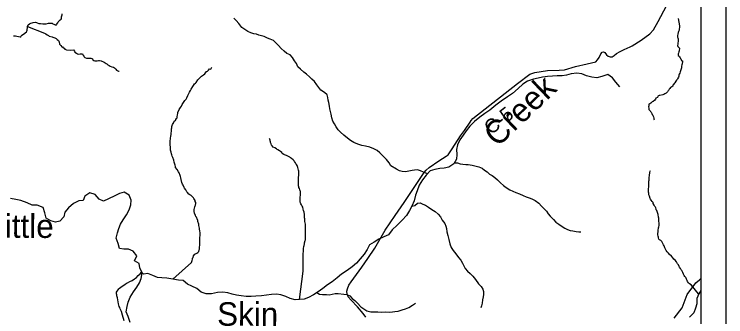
# Model space of a CAD drawing. Extents: x 0 to 34, y 0 to 22.
# Drawn here: x 6.132 to 9, y 19.223 to 20.443 of the extents above; entities that cross this region are included whole.
import ezdxf

# ---------------------------------------------------------------- set-up
doc = ezdxf.new("R2010")
doc.units = 0
for name, color, linetype in [('GM_X_County_Road', 7, 'Continuous'), ('GM_X_County_Road_Text', 7, 'Continuous'), ('GM_X_Minor_River', 7, 'Continuous'), ('GM_X_Minor_River_Text', 7, 'Continuous'), ('GM_X_Township_Road', 7, 'Continuous'), ('SH_Data', 7, 'Continuous')]:
    doc.layers.add(name, color=color, linetype=linetype)

msp = doc.modelspace()

# ---------------------------------------------------------------- linework, layer by layer
at = {"layer": 'GM_X_County_Road'}
for points in [[(8.6142, 20.3116), (8.6222, 20.3154), (8.6587, 20.3383), (8.6939, 20.3635), (8.7082, 20.3797), (8.7282, 20.4138), (8.7614, 20.4759), (8.774, 20.4915)], [(7.9744, 20.0134), (7.9812, 20.0225), (8.1602, 20.1635), (8.2106, 20.2007), (8.2302, 20.2076), (8.2812, 20.2158), (8.3284, 20.2166), (8.3502, 20.2185), (8.394, 20.2311), (8.4412, 20.2427), (8.4762, 20.2506), (8.4834, 20.2588), (8.4895, 20.2685), (8.4959, 20.2823), (8.5023, 20.2893), (8.5076, 20.291), (8.513, 20.2883), (8.5187, 20.2793), (8.5257, 20.2736), (8.5338, 20.2702), (8.5418, 20.2712), (8.5505, 20.2759), (8.5602, 20.2839), (8.575, 20.2927), (8.5902, 20.3), (8.6142, 20.3116)], [(7.549, 19.2211), (7.5381, 19.2359), (7.5159, 19.2631), (7.4908, 19.2899), (7.4785, 19.3026), (7.4742, 19.3142), (7.4735, 19.3262), (7.475, 19.3351), (7.4813, 19.3499), (7.4897, 19.3633), (7.5338, 19.4229), (7.5572, 19.4574), (7.5856, 19.4991), (7.6269, 19.5712), (7.6673, 19.6308), (7.7042, 19.6828), (7.7708, 19.7836), (7.785, 19.8041), (7.7931, 19.8133), (7.8041, 19.8243), (7.8441, 19.8513), (7.8729, 19.8698), (7.8811, 19.8753), (7.8976, 19.8992), (7.9316, 19.9515), (7.9473, 19.9737), (7.9695, 20.0068), (7.9744, 20.0134)], [(8.7925, 19.2167), (8.824, 19.2581), (8.8449, 19.3126), (8.879, 19.3592), (8.8938, 19.3721), (8.9, 19.3763)]]:
    msp.add_lwpolyline(points, dxfattribs=at)
at = {"layer": 'GM_X_Minor_River'}
for points in [[(6.1294, 20.3559), (6.1382, 20.3558), (6.1434, 20.3541), (6.1502, 20.3533), (6.1563, 20.352), (6.1597, 20.3516), (6.1605, 20.3554), (6.1632, 20.358), (6.1693, 20.3621), (6.182, 20.371), (6.1832, 20.3744), (6.184, 20.3781), (6.1844, 20.3808), (6.1849, 20.3838), (6.1857, 20.3869), (6.1857, 20.3895), (6.1865, 20.3933), (6.1877, 20.3975), (6.1889, 20.4001), (6.1935, 20.4031), (6.1993, 20.4064), (6.2054, 20.4082), (6.2092, 20.4092), (6.2183, 20.4102), (6.222, 20.4094), (6.225, 20.4078), (6.2322, 20.4054), (6.2386, 20.4049), (6.2481, 20.4044), (6.2507, 20.4044), (6.2541, 20.4035), (6.2568, 20.4035), (6.2613, 20.4038), (6.2705, 20.4059), (6.2735, 20.4062), (6.278, 20.4062), (6.2856, 20.4064), (6.2878, 20.4033), (6.2916, 20.4018), (6.2969, 20.3994), (6.3014, 20.3986), (6.303, 20.4012), (6.3076, 20.4079), (6.3092, 20.4117), (6.3127, 20.4147), (6.3181, 20.4199), (6.3211, 20.4221), (6.3227, 20.4271), (6.3236, 20.4324), (6.3252, 20.4399), (6.3257, 20.4445)], [(7.798, 19.7994), (7.7817, 19.8061), (7.7693, 19.811), (7.7583, 19.8148), (7.7458, 19.814), (7.736, 19.8125), (7.7227, 19.8091), (7.7087, 19.8072), (7.6955, 19.8087), (7.6856, 19.8114), (7.6731, 19.8182), (7.65, 19.8311), (7.6429, 19.8436), (7.6323, 19.8565), (7.619, 19.8698), (7.6065, 19.8838), (7.5956, 19.8932), (7.5823, 19.8997), (7.5657, 19.9058), (7.5479, 19.9099), (7.5331, 19.9137), (7.5172, 19.9186), (7.5006, 19.9258), (7.4881, 19.9334), (7.476, 19.9429), (7.4605, 19.9554), (7.4469, 19.9675), (7.4378, 19.977), (7.4294, 19.988), (7.4226, 20.0005), (7.417, 20.0115), (7.412, 20.0247), (7.4094, 20.0395), (7.4068, 20.0509), (7.4049, 20.0611), (7.403, 20.0721), (7.4003, 20.0861), (7.3977, 20.0956), (7.3958, 20.1062), (7.3939, 20.1172), (7.3829, 20.1274), (7.3682, 20.1365), (7.3595, 20.1464), (7.3523, 20.1581), (7.3428, 20.1706), (7.3315, 20.1801), (7.3224, 20.1896), (7.3103, 20.2002), (7.2997, 20.2085), (7.2865, 20.2206), (7.2755, 20.2297), (7.2694, 20.2441), (7.2626, 20.2547), (7.2535, 20.2684), (7.2448, 20.279), (7.2316, 20.2847), (7.2202, 20.2937), (7.2085, 20.304), (7.1975, 20.3165), (7.1873, 20.3275), (7.1767, 20.3362), (7.1642, 20.3426), (7.1536, 20.3464), (7.14, 20.3525), (7.1283, 20.3555), (7.1184, 20.3582), (7.1082, 20.3616), (7.098, 20.3638), (7.0859, 20.3669), (7.0738, 20.3726), (7.0621, 20.3805), (7.05, 20.3896), (7.0375, 20.4048), (7.0273, 20.4169), (7.0174, 20.426)], [(8.8087, 20.4253), (8.8133, 20.3951), (8.814, 20.3905), (8.8127, 20.3825), (8.8119, 20.3784), (8.8111, 20.3757), (8.8095, 20.3723), (8.8083, 20.3686), (8.8067, 20.3621), (8.8051, 20.3572), (8.8054, 20.3527), (8.8061, 20.35), (8.8064, 20.3469), (8.8079, 20.3439), (8.8086, 20.3404), (8.8085, 20.3332), (8.8072, 20.3257), (8.8064, 20.3222), (8.8055, 20.3166), (8.8073, 20.3127), (8.8111, 20.3085), (8.8133, 20.3058), (8.8132, 20.3028), (8.812, 20.2978), (8.812, 20.2948), (8.8104, 20.2907), (8.8091, 20.2857), (8.8087, 20.2827), (8.8086, 20.2766), (8.8116, 20.2739), (8.8134, 20.2705), (8.816, 20.2666), (8.8182, 20.2636), (8.823, 20.2547), (8.8256, 20.2539), (8.8259, 20.2479), (8.8247, 20.2452), (8.8239, 20.2418), (8.8231, 20.238), (8.8218, 20.2327), (8.821, 20.227), (8.8186, 20.218), (8.8165, 20.2108), (8.8149, 20.2055), (8.8126, 20.2002), (8.8114, 20.1968), (8.8102, 20.1934), (8.8089, 20.1885), (8.8058, 20.1817), (8.8035, 20.1791), (8.8019, 20.1761), (8.7992, 20.1723), (8.7945, 20.1663), (8.7914, 20.1626), (8.7891, 20.1592), (8.7872, 20.1558), (8.786, 20.1521), (8.7821, 20.1498), (8.7779, 20.1476), (8.7752, 20.1435), (8.7717, 20.1398), (8.7694, 20.1352), (8.7671, 20.1326), (8.7647, 20.1296), (8.7593, 20.1236), (8.754, 20.1214), (8.7505, 20.1192), (8.7467, 20.1181), (8.7346, 20.1149), (8.7311, 20.1142), (8.7262, 20.112), (8.7242, 20.1071), (8.7184, 20.1034), (8.7165, 20.1), (8.7141, 20.0959), (8.7068, 20.0903), (8.703, 20.0893), (8.6984, 20.0833), (8.6942, 20.081), (8.69, 20.08), (8.6899, 20.0731), (8.6887, 20.069), (8.6897, 20.0633), (8.69, 20.0587), (8.6952, 20.0533), (8.6967, 20.0506), (8.6993, 20.0479), (8.7018, 20.0418), (8.7029, 20.0387)], [(6.1865, 20.3933), (6.2542, 20.3663), (6.2595, 20.3636), (6.2655, 20.36), (6.2673, 20.3574), (6.2703, 20.3562), (6.273, 20.3546), (6.2847, 20.351), (6.2884, 20.3505), (6.296, 20.3474), (6.3016, 20.3446), (6.3057, 20.34), (6.3105, 20.3365), (6.3131, 20.3315), (6.3152, 20.322), (6.3174, 20.3189), (6.32, 20.317), (6.3241, 20.3116), (6.3271, 20.3104), (6.3301, 20.3069), (6.3338, 20.305), (6.3368, 20.3011), (6.3432, 20.2991), (6.3576, 20.2977), (6.3712, 20.2986), (6.3757, 20.294), (6.3771, 20.2898), (6.3839, 20.2851), (6.3869, 20.2828), (6.3903, 20.282), (6.3982, 20.2826), (6.4054, 20.2832), (6.4081, 20.2832), (6.4095, 20.279), (6.4125, 20.2748), (6.4136, 20.2717), (6.4176, 20.2675), (6.4241, 20.2658), (6.4278, 20.2658), (6.4328, 20.2653), (6.4407, 20.2648), (6.4456, 20.2639), (6.4482, 20.262), (6.4497, 20.2585), (6.4527, 20.2555), (6.4568, 20.2542), (6.4621, 20.2542), (6.467, 20.2548), (6.4724, 20.2559), (6.4765, 20.2558), (6.4826, 20.2546), (6.4954, 20.2494), (6.5025, 20.2436), (6.5058, 20.242), (6.5099, 20.2382), (6.5144, 20.2358), (6.5185, 20.2327), (6.5253, 20.2303), (6.5325, 20.229), (6.5362, 20.2267), (6.5396, 20.224), (6.5418, 20.2205), (6.544, 20.2163), (6.5527, 20.2135), (6.5552, 20.2131)], [(6.7653, 19.9634), (6.7662, 19.9706), (6.7666, 19.9748), (6.7667, 19.9801), (6.7672, 19.9846), (6.7676, 19.9873), (6.7677, 19.9899), (6.7689, 19.9933), (6.7697, 19.9979), (6.7763, 20.0065), (6.7775, 20.0114), (6.7806, 20.014), (6.7833, 20.0151), (6.7841, 20.0181), (6.7868, 20.0219), (6.7888, 20.0253), (6.7888, 20.0287), (6.7901, 20.0363), (6.7917, 20.0423), (6.7922, 20.0469), (6.7969, 20.0589), (6.8023, 20.0661), (6.807, 20.0721), (6.809, 20.0781), (6.8199, 20.0946), (6.8253, 20.0995), (6.828, 20.1059), (6.832, 20.1149), (6.839, 20.1285), (6.8433, 20.1356), (6.8453, 20.1402), (6.8519, 20.1511), (6.855, 20.1552), (6.8589, 20.1612), (6.8632, 20.1649), (6.8659, 20.1672), (6.8721, 20.1777), (6.8771, 20.1829), (6.8868, 20.1922), (6.8952, 20.1978), (6.9006, 20.2023), (6.9068, 20.2109), (6.9114, 20.2135), (6.9149, 20.2176), (6.9199, 20.2217), (6.9252, 20.2216), (6.9291, 20.2284)], [(8.5724, 20.1498), (8.5566, 20.1681), (8.543, 20.1855), (8.5241, 20.1993), (8.4999, 20.1917), (8.481, 20.1865), (8.4605, 20.1881), (8.4393, 20.1942), (8.4197, 20.2018), (8.4, 20.2042), (8.3765, 20.2019), (8.3584, 20.1974), (8.3402, 20.1945), (8.3205, 20.1945), (8.3016, 20.1931), (8.2811, 20.1908), (8.2614, 20.1886), (8.2433, 20.1841), (8.2258, 20.1811), (8.2016, 20.1729), (8.1826, 20.16), (8.1629, 20.1426), (8.1401, 20.123), (8.1204, 20.1094), (8.0946, 20.0913), (8.0734, 20.0762), (8.0498, 20.0557), (8.0294, 20.0422), (8.0089, 20.0278), (7.9876, 20.0097), (7.9679, 19.9908), (7.9542, 19.9726), (7.942, 19.9552), (7.9284, 19.9363), (7.9185, 19.9158), (7.9154, 19.8976), (7.9161, 19.8771), (7.9145, 19.8574), (7.9046, 19.8392), (7.8834, 19.8264), (7.8652, 19.8212), (7.847, 19.8205), (7.8273, 19.8167), (7.8084, 19.8107), (7.7924, 19.7933), (7.778, 19.7751), (7.765, 19.7539), (7.7559, 19.7305), (7.7498, 19.7123), (7.7436, 19.6895), (7.7353, 19.6691), (7.7254, 19.6509), (7.7132, 19.6305), (7.6965, 19.6123), (7.676, 19.5926), (7.6562, 19.5737), (7.641, 19.5533), (7.6221, 19.545), (7.6024, 19.536), (7.5834, 19.5231), (7.5644, 19.5133), (7.5545, 19.4944), (7.5424, 19.4755), (7.5264, 19.4558), (7.5112, 19.4384), (7.4938, 19.4233), (7.474, 19.4097), (7.4513, 19.3938), (7.4338, 19.3795), (7.4141, 19.3628), (7.3951, 19.3515), (7.3762, 19.3364), (7.358, 19.3235), (7.3382, 19.3115), (7.3178, 19.3009), (7.3003, 19.2941), (7.2822, 19.2919), (7.2648, 19.2904), (7.2443, 19.2966), (7.2269, 19.3042), (7.2065, 19.3111), (7.1891, 19.3134), (7.1687, 19.312), (7.149, 19.3098), (7.1286, 19.3075), (7.1066, 19.3053), (7.0877, 19.3046), (7.0672, 19.3047), (7.0468, 19.307), (7.0286, 19.3101), (7.0105, 19.3132), (6.9931, 19.3186), (6.9727, 19.3224), (6.9522, 19.321), (6.9272, 19.3157), (6.906, 19.315), (6.8864, 19.3219), (6.869, 19.3371), (6.8486, 19.3463), (6.8312, 19.3539), (6.8138, 19.3684)], [(8.7029, 20.0387), (8.7059, 20.0353), (8.7073, 20.0311), (8.7092, 20.0284), (8.7098, 20.023), (8.7102, 20.02), (8.712, 20.0173)], [(6.7715, 19.3738), (6.8463, 19.4413), (6.8479, 19.445), (6.8498, 19.4496), (6.8507, 19.4545), (6.8515, 19.4587), (6.8531, 19.462), (6.8555, 19.4681), (6.8605, 19.4745), (6.8636, 19.4763), (6.8681, 19.4785), (6.8724, 19.4815), (6.8759, 19.4863), (6.8782, 19.492), (6.8787, 19.495), (6.8791, 19.4996), (6.8792, 19.5041), (6.8801, 19.5102), (6.8806, 19.5212), (6.881, 19.5425), (6.8819, 19.5504), (6.8817, 19.5615), (6.8803, 19.5691), (6.8797, 19.5755), (6.8794, 19.5801), (6.8769, 19.5912), (6.8759, 19.5965), (6.873, 19.6068), (6.872, 19.6106), (6.8694, 19.6175), (6.8684, 19.6206), (6.8673, 19.6236), (6.8647, 19.6275), (6.8625, 19.6328), (6.8603, 19.6363), (6.8589, 19.6401), (6.8579, 19.6473), (6.8575, 19.6515), (6.8576, 19.6553), (6.8597, 19.6659), (6.8617, 19.6697), (6.8632, 19.6723), (6.8649, 19.6791), (6.8642, 19.6829), (6.8623, 19.6875), (6.8616, 19.6909), (6.8569, 19.699), (6.8547, 19.7021), (6.8524, 19.7048), (6.8453, 19.7114), (6.8405, 19.7145), (6.8367, 19.7168), (6.8308, 19.7241), (6.8286, 19.7268), (6.8249, 19.7318), (6.8234, 19.7345), (6.819, 19.7407), (6.8171, 19.7441), (6.8131, 19.7529), (6.8106, 19.7579), (6.8084, 19.7636), (6.8052, 19.7766), (6.8034, 19.7827), (6.802, 19.7877), (6.8013, 19.7919), (6.7973, 19.8029), (6.7948, 19.8075), (6.7892, 19.816), (6.7829, 19.8245), (6.7823, 19.829), (6.7808, 19.8336), (6.7779, 19.8413), (6.7773, 19.8454), (6.7751, 19.8535), (6.7719, 19.8649), (6.7694, 19.8706), (6.7672, 19.8756), (6.7665, 19.8794), (6.7643, 19.8859), (6.7629, 19.8897), (6.7622, 19.8943), (6.7619, 19.8981), (6.7617, 19.9072), (6.761, 19.9141), (6.7608, 19.9213), (6.7609, 19.9274), (6.7627, 19.9437), (6.7632, 19.9494), (6.7649, 19.9592), (6.7653, 19.9634)], [(7.2109, 19.8844), (7.2049, 19.8891), (7.2012, 19.8918), (7.1952, 19.8957), (7.1922, 19.8973), (7.1888, 19.8996), (7.1824, 19.9035), (7.1757, 19.907), (7.1723, 19.9113), (7.1697, 19.9143), (7.1679, 19.9197), (7.1654, 19.9254), (7.1647, 19.9281), (7.164, 19.9323), (7.1637, 19.935), (7.1622, 19.9384), (7.1608, 19.9413)], [(7.2822, 19.2925), (7.2968, 19.4062), (7.2965, 19.4138), (7.2967, 19.426), (7.2965, 19.4363), (7.2966, 19.4401), (7.2971, 19.4442), (7.2973, 19.4556), (7.297, 19.4602), (7.2972, 19.472), (7.2969, 19.4788), (7.2978, 19.4849), (7.298, 19.4947), (7.2984, 19.4985), (7.2993, 19.5057), (7.3005, 19.5106), (7.3017, 19.5163), (7.3022, 19.5205), (7.3046, 19.5296), (7.3058, 19.5322), (7.3063, 19.5383), (7.3066, 19.5561), (7.3063, 19.5622), (7.306, 19.5668), (7.3061, 19.5713), (7.3062, 19.5782), (7.3063, 19.5823), (7.3061, 19.5896), (7.3062, 19.596), (7.3051, 19.601), (7.3041, 19.6071), (7.3034, 19.6112), (7.3031, 19.6177), (7.3028, 19.6211), (7.3022, 19.6291), (7.3019, 19.6352), (7.3006, 19.6447), (7.2988, 19.6512), (7.2974, 19.6569), (7.2953, 19.6646), (7.2934, 19.6688), (7.2897, 19.6742), (7.2872, 19.678), (7.2857, 19.6818), (7.2854, 19.6845), (7.2844, 19.6913), (7.2845, 19.6963), (7.2853, 19.7016), (7.2854, 19.705), (7.2859, 19.7126), (7.286, 19.7221), (7.2858, 19.7282), (7.2854, 19.7308), (7.284, 19.7339), (7.2822, 19.7392), (7.28, 19.7438), (7.2793, 19.7465), (7.2786, 19.7499), (7.2775, 19.7534), (7.2776, 19.7575), (7.2784, 19.7625), (7.2785, 19.767), (7.2782, 19.7697), (7.2779, 19.7784), (7.2784, 19.7853), (7.2793, 19.7928), (7.2795, 19.8012), (7.2796, 19.8054), (7.2789, 19.8103), (7.2782, 19.8134), (7.2764, 19.8191), (7.2753, 19.8241), (7.2721, 19.8328), (7.2699, 19.8363), (7.2669, 19.8398), (7.2662, 19.8428), (7.2625, 19.8482), (7.2603, 19.8513), (7.2562, 19.8548), (7.2498, 19.8602), (7.2457, 19.8633), (7.2427, 19.8656), (7.2356, 19.8703), (7.2296, 19.8727), (7.2221, 19.8759), (7.2195, 19.8774), (7.2123, 19.8813), (7.2109, 19.8844)], [(7.9069, 19.8436), (7.9195, 19.8428), (7.9301, 19.839), (7.9403, 19.8375), (7.9521, 19.8364), (7.9623, 19.8364), (7.9782, 19.8333), (7.9884, 19.8311), (8.0054, 19.8277), (8.0179, 19.822), (8.0278, 19.814), (8.038, 19.8064), (8.0478, 19.7977), (8.0592, 19.7924), (8.069, 19.7841), (8.0804, 19.775), (8.0917, 19.7632), (8.1042, 19.7519), (8.1155, 19.7439), (8.1303, 19.7341), (8.1416, 19.7295), (8.1541, 19.7242), (8.1693, 19.7181), (8.1833, 19.7117), (8.1958, 19.7068), (8.2083, 19.7022), (8.2188, 19.6981), (8.2313, 19.6912), (8.2461, 19.6802), (8.2571, 19.6689), (8.2673, 19.6594), (8.2771, 19.6488), (8.2847, 19.637), (8.2922, 19.6276), (8.3051, 19.6147), (8.3157, 19.6037), (8.3274, 19.5954), (8.3407, 19.5867), (8.3509, 19.5802), (8.3619, 19.5741), (8.3728, 19.5704), (8.3838, 19.5688), (8.3974, 19.5669), (8.4073, 19.5654), (8.416, 19.5647)], [(8.8906, 19.3147), (8.8605, 19.3512), (8.8541, 19.3551), (8.8497, 19.3597), (8.8464, 19.3651), (8.8438, 19.3693), (8.8423, 19.3743), (8.8409, 19.3781), (8.8387, 19.3808), (8.8353, 19.385), (8.8324, 19.3885), (8.8298, 19.3946), (8.8273, 19.4015), (8.8225, 19.4088), (8.8207, 19.4123), (8.8181, 19.4172), (8.814, 19.4223), (8.8126, 19.4249), (8.8089, 19.4318), (8.8052, 19.4361), (8.8026, 19.4411), (8.8012, 19.4445), (8.796, 19.4507), (8.7907, 19.4549), (8.7878, 19.4588), (8.7815, 19.4665), (8.7733, 19.4731), (8.7692, 19.4785), (8.7644, 19.485), (8.7599, 19.4893), (8.7573, 19.4946), (8.7555, 19.4977), (8.7544, 19.5008), (8.7515, 19.508), (8.7486, 19.5126), (8.746, 19.5184), (8.742, 19.526), (8.7379, 19.5295), (8.7323, 19.533), (8.73, 19.5361), (8.729, 19.5403), (8.7283, 19.543), (8.7272, 19.5479), (8.7266, 19.5533), (8.7267, 19.559), (8.7272, 19.5654), (8.7276, 19.5711), (8.7289, 19.5806), (8.7302, 19.5851), (8.731, 19.5912), (8.7315, 19.5946), (8.7311, 19.598), (8.7312, 19.6011), (8.7309, 19.6071), (8.7302, 19.6113), (8.7296, 19.617), (8.7296, 19.6201), (8.7289, 19.6243), (8.7286, 19.6273), (8.7279, 19.6319), (8.7276, 19.6345), (8.7266, 19.6387), (8.7247, 19.6426), (8.7222, 19.6506), (8.72, 19.6544), (8.7189, 19.6571), (8.7179, 19.6613), (8.7168, 19.664), (8.7146, 19.6678), (8.7116, 19.6724), (8.7079, 19.6793), (8.7073, 19.6827), (8.7028, 19.687), (8.6999, 19.6928), (8.6969, 19.6966), (8.6951, 19.7), (8.6926, 19.7084), (8.6904, 19.7138), (8.6894, 19.721), (8.6891, 19.7256), (8.6888, 19.7336), (8.6889, 19.7397), (8.6894, 19.7453), (8.6895, 19.751), (8.69, 19.7556), (8.6902, 19.7689), (8.6907, 19.7731), (8.6908, 19.7799), (8.6916, 19.786), (8.6921, 19.7905), (8.6925, 19.7943), (8.693, 19.7977), (8.6934, 19.8004)], [(8.6934, 19.8004), (8.6942, 19.8038), (8.6955, 19.8091), (8.6966, 19.8119)], [(6.5999, 19.1999), (6.5916, 19.2234), (6.5841, 19.2424), (6.5872, 19.2636), (6.591, 19.2818), (6.6002, 19.3023), (6.6131, 19.3235), (6.6268, 19.3417), (6.6374, 19.3598), (6.6443, 19.3773), (6.6474, 19.3992), (6.6391, 19.4198), (6.6354, 19.4372), (6.6173, 19.4486), (6.6264, 19.4683), (6.6121, 19.4866), (6.5932, 19.4957), (6.5743, 19.495), (6.5569, 19.4981), (6.5516, 19.5186), (6.5434, 19.5391), (6.5487, 19.5611), (6.5541, 19.5785), (6.561, 19.596), (6.5709, 19.6134), (6.5846, 19.6338), (6.5952, 19.6535), (6.6021, 19.674), (6.6037, 19.6929), (6.5962, 19.7127), (6.5758, 19.7249), (6.5568, 19.7196), (6.5379, 19.7106), (6.5121, 19.6977), (6.4924, 19.6887), (6.4742, 19.6963), (6.4584, 19.7154), (6.4372, 19.7222), (6.4167, 19.7094), (6.4106, 19.6912), (6.3932, 19.6905), (6.3712, 19.6792), (6.3515, 19.6618), (6.3363, 19.6437), (6.3325, 19.6255), (6.3165, 19.6081), (6.2991, 19.6036), (6.2794, 19.6089), (6.2613, 19.6204), (6.2553, 19.6416), (6.2485, 19.6629), (6.2244, 19.6728), (6.2054, 19.6729), (6.185, 19.682), (6.1593, 19.6912), (6.1389, 19.6958), (6.1177, 19.6997)], [(7.735, 19.6687), (7.7469, 19.6708), (7.7582, 19.6803), (7.7685, 19.6814), (7.7794, 19.6769), (7.7897, 19.672), (7.8014, 19.6651), (7.815, 19.6557), (7.829, 19.6466), (7.8415, 19.6367), (7.8498, 19.625), (7.857, 19.6125), (7.8676, 19.5984), (7.8721, 19.5878), (7.874, 19.578), (7.8763, 19.5651), (7.8797, 19.5507), (7.8835, 19.5348), (7.8876, 19.517), (7.8933, 19.5014), (7.9009, 19.4893), (7.9115, 19.4768), (7.9224, 19.462), (7.9319, 19.4507), (7.9387, 19.4385), (7.944, 19.4275), (7.9504, 19.4173), (7.9595, 19.4067), (7.9697, 19.3969), (7.9807, 19.3866), (7.9913, 19.3726), (8.003, 19.3548), (8.0136, 19.3446), (8.0212, 19.3339), (8.0235, 19.3245), (8.0238, 19.3127), (8.0227, 19.3029), (8.02, 19.2915), (8.0178, 19.2775), (8.0162, 19.2665), (8.0128, 19.2589)], [(6.8138, 19.3684), (6.7942, 19.37), (6.7715, 19.3738), (6.7473, 19.3777), (6.7268, 19.3793), (6.7094, 19.3809), (6.6905, 19.3893), (6.6709, 19.3977), (6.6534, 19.3947), (6.6474, 19.3992)], [(8.9, 19.3283), (8.8908, 19.3145), (8.8831, 19.2956), (8.8838, 19.2743), (8.8785, 19.2569), (8.8709, 19.2387), (8.8534, 19.2205)], [(7.3523, 19.3201), (7.3623, 19.3132), (7.3748, 19.3124), (7.3903, 19.3121), (7.402, 19.3109), (7.4141, 19.314), (7.4258, 19.3158), (7.438, 19.3158), (7.4607, 19.3136), (7.4735, 19.312), (7.4856, 19.3067), (7.4947, 19.2958), (7.5046, 19.2882), (7.5163, 19.2776), (7.5292, 19.262), (7.5416, 19.2541), (7.5538, 19.2469), (7.5693, 19.2431), (7.5984, 19.2431), (7.6135, 19.2415), (7.6302, 19.2423), (7.6434, 19.2415), (7.6563, 19.2419), (7.6665, 19.2434), (7.6794, 19.2449), (7.6957, 19.2502), (7.7093, 19.254), (7.7233, 19.2605), (7.7373, 19.2692), (7.7494, 19.2771)]]:
    msp.add_lwpolyline(points, dxfattribs=at)
at = {"layer": 'GM_X_Township_Road'}
for points in [[(6.5447, 19.3223), (6.5534, 19.335), (6.5573, 19.3385), (6.5675, 19.3456), (6.5781, 19.3533), (6.585, 19.3575), (6.5894, 19.3598), (6.5988, 19.3642), (6.6083, 19.3692), (6.6175, 19.3754), (6.6254, 19.3815), (6.6319, 19.3886), (6.6395, 19.3963), (6.6451, 19.403)], [(6.5749, 19.2067), (6.5686, 19.2289), (6.5641, 19.2439), (6.5622, 19.2489), (6.5596, 19.2552), (6.5575, 19.2603), (6.5555, 19.2644), (6.5522, 19.275), (6.5498, 19.2906), (6.5485, 19.2984), (6.5476, 19.3024), (6.5463, 19.3074), (6.5455, 19.3114), (6.5451, 19.3152), (6.5447, 19.3223)]]:
    msp.add_lwpolyline(points, dxfattribs=at)
at = {"layer": 'SH_Data'}
for p, q in [((9, 21), (9, 14)), ((8.9, 20.9), (8.9, 14.1))]:
    msp.add_line(p, q, dxfattribs=at)

# ---------------------------------------------------------------- texts
at = {"layer": 'GM_X_County_Road_Text'}
msp.add_text('C-5', height=0.05682, rotation=38.2345, dxfattribs=at).set_placement((8.0541, 19.9539))
at = {"layer": 'GM_X_Minor_River_Text'}
for s, rotation, p in [('Creek', 43.7586, (8.0802, 19.9032)), ('Little', 359.7569, (6.0239, 19.5415)), ('Skin', 359.754, (6.9499, 19.1867))]:
    msp.add_text(s, height=0.09469, rotation=rotation, dxfattribs=at).set_placement(p)

doc.saveas('drawing.dxf')
